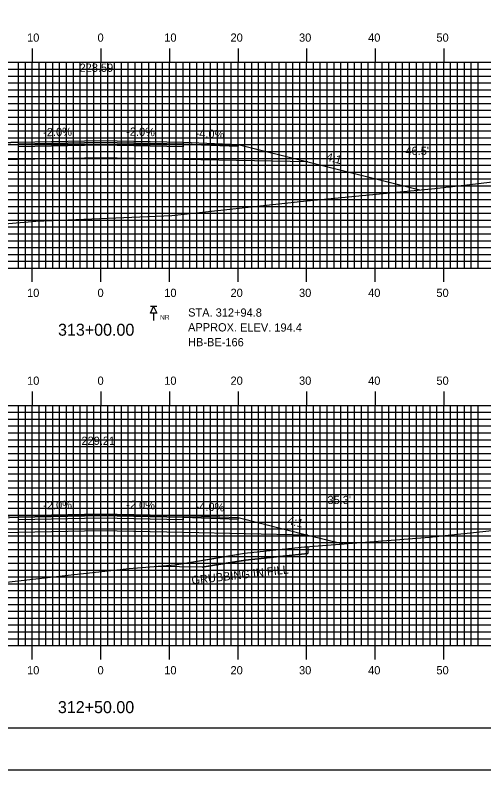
# Model space of a CAD drawing. Extents: x 1818850 to 1819194, y 442591 to 442811.
# Drawn here: x 1819003.7 to 1819072, y 442590.5 to 442700.5 of the extents above; entities that cross this region are included whole.
import ezdxf

# ---------------------------------------------------------------- set-up
doc = ezdxf.new("R2010")
doc.units = 0
for name, color, linetype in [('ANNOTATION', 7, 'Continuous'), ('BORDER', 7, 'Continuous'), ('BORING - NO REFUSAL', 7, 'Continuous'), ('D_Roadway_Centerline', 7, 'Continuous'), ('D_Roadway_Centerline_Text', 7, 'Continuous'), ('D_Roadway_Edge_Shoulder', 7, 'Continuous'), ('D_Roadway_Edge_TW', 7, 'Continuous'), ('D_Roadway_Pavement', 7, 'Continuous'), ('D_Roadway_SlopeLines', 7, 'Continuous'), ('D_Roadway_SubGrade', 7, 'Continuous'), ('D_Text_Standard', 7, 'Continuous'), ('GRUBBING IN FILL', 7, 'Continuous'), ('H_V ANNOTATION', 7, 'Continuous'), ('MAJOR', 7, 'Continuous'), ('MINOR', 7, 'Continuous'), ('PLOT BOUNDARY', 7, 'Continuous'), ('S_Roadway_Centerline', 7, 'Continuous')]:
    doc.layers.add(name, color=color, linetype=linetype)

msp = doc.modelspace()

# ---------------------------------------------------------------- linework, layer by layer
at = {"layer": 'BORDER'}
msp.add_lwpolyline([(1818866.55, 442596.67), (1819186.55, 442596.67), (1819186.55, 442806.67), (1818866.55, 442806.67)], close=True, dxfattribs=at)
at = {"layer": 'BORING - NO REFUSAL'}
for p, q in [((1819024.33, 442658.07), (1819023.37, 442658.07)), ((1819023.85, 442657.11), (1819023.85, 442656.05))]:
    msp.add_line(p, q, dxfattribs=at)
msp.add_lwpolyline([(1819023.85, 442658.07), (1819024.33, 442657.11), (1819023.37, 442657.11)], close=True, dxfattribs=at)
at = {"layer": 'D_Roadway_Centerline'}
for points in [[(1818957.09, 442669.67), (1818984.15, 442678.69), (1818985.98, 442679.15), (1818996.15, 442681.69), (1819004.15, 442682.01), (1819016.15, 442682.25), (1819028.15, 442682.01), (1819036.15, 442681.69), (1819046.33, 442679.15), (1819062.68, 442675.06)], [(1818954.03, 442614.28), (1818984.15, 442624.32), (1818985.98, 442624.77), (1818996.15, 442627.32), (1819004.15, 442627.64), (1819016.15, 442627.88), (1819028.15, 442627.64), (1819036.15, 442627.32), (1819046.33, 442624.77), (1819051.46, 442623.49)]]:
    msp.add_lwpolyline(points, dxfattribs=at)
at = {"layer": 'D_Roadway_Edge_Shoulder'}
for points in [[(1819004.15, 442682.01), (1818996.15, 442681.69), (1818996.15, 442681.44), (1819004.15, 442681.76)], [(1819028.15, 442682.01), (1819036.15, 442681.69), (1819036.15, 442681.44), (1819028.15, 442681.76)], [(1819004.15, 442627.64), (1818996.15, 442627.32), (1818996.15, 442627.07), (1819004.15, 442627.39)], [(1819028.15, 442627.64), (1819036.15, 442627.32), (1819036.15, 442627.07), (1819028.15, 442627.39)]]:
    msp.add_lwpolyline(points, close=True, dxfattribs=at)
at = {"layer": 'D_Roadway_Edge_TW'}
for points in [[(1819004.15, 442681.76), (1819004.15, 442682.01), (1819016.15, 442682.25), (1819028.15, 442682.01), (1819028.15, 442681.76), (1819016.15, 442682)], [(1819004.15, 442627.39), (1819004.15, 442627.64), (1819016.15, 442627.88), (1819028.15, 442627.64), (1819028.15, 442627.39), (1819016.15, 442627.63)]]:
    msp.add_lwpolyline(points, close=True, dxfattribs=at)
at = {"layer": 'D_Roadway_Pavement'}
for points in [[(1819004.15, 442681.34), (1819004.15, 442681.76), (1819016.15, 442682), (1819028.15, 442681.76), (1819028.15, 442681.34), (1819016.15, 442681.58)], [(1819004.15, 442626.97), (1819004.15, 442627.39), (1819016.15, 442627.63), (1819028.15, 442627.39), (1819028.15, 442626.97), (1819016.15, 442627.21)]]:
    msp.add_lwpolyline(points, close=True, dxfattribs=at)
at = {"layer": 'D_Roadway_SlopeLines'}
for points in [[(1819036.15, 442681.69), (1819046.33, 442679.15), (1819062.68, 442675.06)], [(1819036.15, 442627.32), (1819046.33, 442624.77), (1819051.46, 442623.49)]]:
    msp.add_lwpolyline(points, dxfattribs=at)
at = {"layer": 'D_Roadway_SubGrade'}
for points in [[(1819004.15, 442679.51), (1818985.98, 442679.15), (1818996.15, 442681.69), (1818996.15, 442681.44), (1819004.15, 442681.76), (1819016.15, 442682), (1819028.15, 442681.76), (1819036.15, 442681.44), (1819036.15, 442681.69), (1819046.33, 442679.15), (1819028.15, 442679.51), (1819016.15, 442679.75)], [(1819004.15, 442625.14), (1818985.98, 442624.77), (1818996.15, 442627.32), (1818996.15, 442627.07), (1819004.15, 442627.39), (1819016.15, 442627.63), (1819028.15, 442627.39), (1819036.15, 442627.07), (1819036.15, 442627.32), (1819046.33, 442624.77), (1819028.15, 442625.14), (1819016.15, 442625.38)]]:
    msp.add_lwpolyline(points, close=True, dxfattribs=at)
at = {"layer": 'GRUBBING IN FILL'}
msp.add_line((1819046.33, 442623.09), (1819046.33, 442622.08), dxfattribs=at)
msp.add_line((1819046.33, 442623.09), (1819046.33, 442622.08), dxfattribs=at)
msp.add_lwpolyline([(1819046.33, 442623.09), (1819046.33, 442622.08), (1819041.33, 442621.57), (1819037.22, 442621.13), (1819034.08, 442620.61), (1819030.94, 442620.08), (1819024.31, 442620.21), (1819026.94, 442620.43), (1819032.02, 442621.27), (1819037.09, 442622.12), (1819041.21, 442622.56), (1819045.34, 442623.01)], close=True, dxfattribs=at)
msp.add_lwpolyline([(1819046.33, 442623.09), (1819046.33, 442622.08), (1819041.33, 442621.57), (1819037.22, 442621.13), (1819034.08, 442620.61), (1819030.94, 442620.08), (1819024.31, 442620.21), (1819026.94, 442620.43), (1819032.02, 442621.27), (1819037.09, 442622.12), (1819041.21, 442622.56), (1819045.34, 442623.01)], close=True, dxfattribs=at)
msp.add_lwpolyline([(1819030.94, 442620.08), (1819037.22, 442621.13), (1819045.43, 442622.01), (1819046.33, 442622.08)], dxfattribs=at)
msp.add_lwpolyline([(1819030.94, 442620.08), (1819037.22, 442621.13), (1819045.43, 442622.01), (1819046.33, 442622.08)], dxfattribs=at)
at = {"layer": 'MAJOR'}
for p, q in [((1819006.15, 442695.67), (1819006.15, 442693.67)), ((1819016.15, 442695.67), (1819016.15, 442693.67)), ((1819026.15, 442695.67), (1819026.15, 442693.67)), ((1819036.15, 442695.67), (1819036.15, 442693.67)), ((1819046.15, 442695.67), (1819046.15, 442693.67)), ((1819056.15, 442695.67), (1819056.15, 442693.67)), ((1819066.15, 442695.67), (1819066.15, 442693.67)), ((1818876.15, 442693.67), (1819156.15, 442693.67)), ((1818876.15, 442693.67), (1819156.15, 442693.67)), ((1819006.15, 442663.67), (1819006.15, 442693.67)), ((1819016.15, 442663.67), (1819016.15, 442693.67)), ((1819026.15, 442663.67), (1819026.15, 442693.67)), ((1819036.15, 442663.67), (1819036.15, 442693.67)), ((1819046.15, 442663.67), (1819046.15, 442693.67)), ((1819056.15, 442663.67), (1819056.15, 442693.67)), ((1819066.15, 442663.67), (1819066.15, 442693.67)), ((1818876.15, 442688.67), (1819156.15, 442688.67)), ((1818876.15, 442683.67), (1819156.15, 442683.67)), ((1818876.15, 442678.67), (1819156.15, 442678.67)), ((1818876.15, 442673.67), (1819156.15, 442673.67)), ((1818876.15, 442668.67), (1819156.15, 442668.67)), ((1818876.15, 442663.67), (1819156.15, 442663.67)), ((1818876.15, 442663.67), (1819156.15, 442663.67)), ((1819006.15, 442661.66), (1819006.15, 442663.67)), ((1819016.15, 442661.66), (1819016.15, 442663.67)), ((1819026.15, 442661.66), (1819026.15, 442663.67)), ((1819036.15, 442661.66), (1819036.15, 442663.67)), ((1819046.15, 442661.66), (1819046.15, 442663.67)), ((1819056.15, 442661.66), (1819056.15, 442663.67)), ((1819066.15, 442661.66), (1819066.15, 442663.67)), ((1819006.15, 442645.67), (1819006.15, 442643.67)), ((1819016.15, 442645.67), (1819016.15, 442643.67)), ((1819026.15, 442645.67), (1819026.15, 442643.67)), ((1819036.15, 442645.67), (1819036.15, 442643.67)), ((1819046.15, 442645.67), (1819046.15, 442643.67)), ((1819056.15, 442645.67), (1819056.15, 442643.67)), ((1819066.15, 442645.67), (1819066.15, 442643.67)), ((1818876.15, 442643.67), (1819156.15, 442643.67)), ((1818876.15, 442643.67), (1819156.15, 442643.67)), ((1819006.15, 442608.67), (1819006.15, 442643.67)), ((1819016.15, 442608.67), (1819016.15, 442643.67)), ((1819026.15, 442608.67), (1819026.15, 442643.67)), ((1819036.15, 442608.67), (1819036.15, 442643.67)), ((1819046.15, 442608.67), (1819046.15, 442643.67)), ((1819056.15, 442608.67), (1819056.15, 442643.67)), ((1819066.15, 442608.67), (1819066.15, 442643.67)), ((1818876.15, 442638.67), (1819156.15, 442638.67)), ((1818876.15, 442633.67), (1819156.15, 442633.67)), ((1818876.15, 442628.67), (1819156.15, 442628.67)), ((1818876.15, 442623.67), (1819156.15, 442623.67)), ((1818876.15, 442618.67), (1819156.15, 442618.67)), ((1818876.15, 442613.67), (1819156.15, 442613.67)), ((1818876.15, 442608.67), (1819156.15, 442608.67)), ((1818876.15, 442608.67), (1819156.15, 442608.67)), ((1819006.15, 442606.66), (1819006.15, 442608.67)), ((1819016.15, 442606.66), (1819016.15, 442608.67)), ((1819026.15, 442606.66), (1819026.15, 442608.67)), ((1819036.15, 442606.66), (1819036.15, 442608.67)), ((1819046.15, 442606.66), (1819046.15, 442608.67)), ((1819056.15, 442606.66), (1819056.15, 442608.67)), ((1819066.15, 442606.66), (1819066.15, 442608.67))]:
    msp.add_line(p, q, dxfattribs=at)
at = {"layer": 'MINOR'}
for p, q in [((1819004.15, 442663.67), (1819004.15, 442693.67)), ((1819005.15, 442663.67), (1819005.15, 442693.67)), ((1819007.15, 442663.67), (1819007.15, 442693.67)), ((1819008.15, 442663.67), (1819008.15, 442693.67)), ((1819009.15, 442663.67), (1819009.15, 442693.67)), ((1819010.15, 442663.67), (1819010.15, 442693.67)), ((1819011.15, 442663.67), (1819011.15, 442693.67)), ((1819012.15, 442663.67), (1819012.15, 442693.67)), ((1819013.15, 442663.67), (1819013.15, 442693.67)), ((1819014.15, 442663.67), (1819014.15, 442693.67)), ((1819015.15, 442663.67), (1819015.15, 442693.67)), ((1819017.15, 442663.67), (1819017.15, 442693.67)), ((1819018.15, 442663.67), (1819018.15, 442693.67)), ((1819019.15, 442663.67), (1819019.15, 442693.67)), ((1819020.15, 442663.67), (1819020.15, 442693.67)), ((1819021.15, 442663.67), (1819021.15, 442693.67)), ((1819022.15, 442663.67), (1819022.15, 442693.67)), ((1819023.15, 442663.67), (1819023.15, 442693.67)), ((1819024.15, 442663.67), (1819024.15, 442693.67)), ((1819025.15, 442663.67), (1819025.15, 442693.67)), ((1819027.15, 442663.67), (1819027.15, 442693.67)), ((1819028.15, 442663.67), (1819028.15, 442693.67)), ((1819029.15, 442663.67), (1819029.15, 442693.67)), ((1819030.15, 442663.67), (1819030.15, 442693.67)), ((1819031.15, 442663.67), (1819031.15, 442693.67)), ((1819032.15, 442663.67), (1819032.15, 442693.67)), ((1819033.15, 442663.67), (1819033.15, 442693.67)), ((1819034.15, 442663.67), (1819034.15, 442693.67)), ((1819035.15, 442663.67), (1819035.15, 442693.67)), ((1819037.15, 442663.67), (1819037.15, 442693.67)), ((1819038.15, 442663.67), (1819038.15, 442693.67)), ((1819039.15, 442663.67), (1819039.15, 442693.67)), ((1819040.15, 442663.67), (1819040.15, 442693.67)), ((1819041.15, 442663.67), (1819041.15, 442693.67)), ((1819042.15, 442663.67), (1819042.15, 442693.67)), ((1819043.15, 442663.67), (1819043.15, 442693.67)), ((1819044.15, 442663.67), (1819044.15, 442693.67)), ((1819045.15, 442663.67), (1819045.15, 442693.67)), ((1819047.15, 442663.67), (1819047.15, 442693.67)), ((1819048.15, 442663.67), (1819048.15, 442693.67)), ((1819049.15, 442663.67), (1819049.15, 442693.67)), ((1819050.15, 442663.67), (1819050.15, 442693.67)), ((1819051.15, 442663.67), (1819051.15, 442693.67)), ((1819052.15, 442663.67), (1819052.15, 442693.67)), ((1819053.15, 442663.67), (1819053.15, 442693.67)), ((1819054.15, 442663.67), (1819054.15, 442693.67)), ((1819055.15, 442663.67), (1819055.15, 442693.67)), ((1819057.15, 442663.67), (1819057.15, 442693.67)), ((1819058.15, 442663.67), (1819058.15, 442693.67)), ((1819059.15, 442663.67), (1819059.15, 442693.67)), ((1819060.15, 442663.67), (1819060.15, 442693.67)), ((1819061.15, 442663.67), (1819061.15, 442693.67)), ((1819062.15, 442663.67), (1819062.15, 442693.67)), ((1819063.15, 442663.67), (1819063.15, 442693.67)), ((1819064.15, 442663.67), (1819064.15, 442693.67)), ((1819065.15, 442663.67), (1819065.15, 442693.67)), ((1819067.15, 442663.67), (1819067.15, 442693.67)), ((1819068.15, 442663.67), (1819068.15, 442693.67)), ((1819069.15, 442663.67), (1819069.15, 442693.67)), ((1819070.15, 442663.67), (1819070.15, 442693.67)), ((1819071.15, 442663.67), (1819071.15, 442693.67)), ((1818876.15, 442692.67), (1819156.15, 442692.67)), ((1818876.15, 442691.67), (1819156.15, 442691.67)), ((1818876.15, 442690.67), (1819156.15, 442690.67)), ((1818876.15, 442689.67), (1819156.15, 442689.67)), ((1818876.15, 442687.67), (1819156.15, 442687.67)), ((1818876.15, 442686.67), (1819156.15, 442686.67)), ((1818876.15, 442685.67), (1819156.15, 442685.67)), ((1818876.15, 442684.67), (1819156.15, 442684.67)), ((1818876.15, 442682.67), (1819156.15, 442682.67)), ((1818876.15, 442681.67), (1819156.15, 442681.67)), ((1818876.15, 442680.67), (1819156.15, 442680.67)), ((1818876.15, 442679.67), (1819156.15, 442679.67)), ((1818876.15, 442677.67), (1819156.15, 442677.67)), ((1818876.15, 442676.67), (1819156.15, 442676.67)), ((1818876.15, 442675.67), (1819156.15, 442675.67)), ((1818876.15, 442674.67), (1819156.15, 442674.67)), ((1818876.15, 442672.67), (1819156.15, 442672.67)), ((1818876.15, 442671.67), (1819156.15, 442671.67)), ((1818876.15, 442670.67), (1819156.15, 442670.67)), ((1818876.15, 442669.67), (1819156.15, 442669.67)), ((1818876.15, 442667.67), (1819156.15, 442667.67)), ((1818876.15, 442666.67), (1819156.15, 442666.67)), ((1818876.15, 442665.67), (1819156.15, 442665.67)), ((1818876.15, 442664.67), (1819156.15, 442664.67)), ((1819004.15, 442608.67), (1819004.15, 442643.67)), ((1819005.15, 442608.67), (1819005.15, 442643.67)), ((1819007.15, 442608.67), (1819007.15, 442643.67)), ((1819008.15, 442608.67), (1819008.15, 442643.67)), ((1819009.15, 442608.67), (1819009.15, 442643.67)), ((1819010.15, 442608.67), (1819010.15, 442643.67)), ((1819011.15, 442608.67), (1819011.15, 442643.67)), ((1819012.15, 442608.67), (1819012.15, 442643.67)), ((1819013.15, 442608.67), (1819013.15, 442643.67)), ((1819014.15, 442608.67), (1819014.15, 442643.67)), ((1819015.15, 442608.67), (1819015.15, 442643.67)), ((1819017.15, 442608.67), (1819017.15, 442643.67)), ((1819018.15, 442608.67), (1819018.15, 442643.67)), ((1819019.15, 442608.67), (1819019.15, 442643.67)), ((1819020.15, 442608.67), (1819020.15, 442643.67)), ((1819021.15, 442608.67), (1819021.15, 442643.67)), ((1819022.15, 442608.67), (1819022.15, 442643.67)), ((1819023.15, 442608.67), (1819023.15, 442643.67)), ((1819024.15, 442608.67), (1819024.15, 442643.67)), ((1819025.15, 442608.67), (1819025.15, 442643.67)), ((1819027.15, 442608.67), (1819027.15, 442643.67)), ((1819028.15, 442608.67), (1819028.15, 442643.67)), ((1819029.15, 442608.67), (1819029.15, 442643.67)), ((1819030.15, 442608.67), (1819030.15, 442643.67)), ((1819031.15, 442608.67), (1819031.15, 442643.67)), ((1819032.15, 442608.67), (1819032.15, 442643.67)), ((1819033.15, 442608.67), (1819033.15, 442643.67)), ((1819034.15, 442608.67), (1819034.15, 442643.67)), ((1819035.15, 442608.67), (1819035.15, 442643.67)), ((1819037.15, 442608.67), (1819037.15, 442643.67)), ((1819038.15, 442608.67), (1819038.15, 442643.67)), ((1819039.15, 442608.67), (1819039.15, 442643.67)), ((1819040.15, 442608.67), (1819040.15, 442643.67)), ((1819041.15, 442608.67), (1819041.15, 442643.67)), ((1819042.15, 442608.67), (1819042.15, 442643.67)), ((1819043.15, 442608.67), (1819043.15, 442643.67)), ((1819044.15, 442608.67), (1819044.15, 442643.67)), ((1819045.15, 442608.67), (1819045.15, 442643.67)), ((1819047.15, 442608.67), (1819047.15, 442643.67)), ((1819048.15, 442608.67), (1819048.15, 442643.67)), ((1819049.15, 442608.67), (1819049.15, 442643.67)), ((1819050.15, 442608.67), (1819050.15, 442643.67)), ((1819051.15, 442608.67), (1819051.15, 442643.67)), ((1819052.15, 442608.67), (1819052.15, 442643.67)), ((1819053.15, 442608.67), (1819053.15, 442643.67)), ((1819054.15, 442608.67), (1819054.15, 442643.67)), ((1819055.15, 442608.67), (1819055.15, 442643.67)), ((1819057.15, 442608.67), (1819057.15, 442643.67)), ((1819058.15, 442608.67), (1819058.15, 442643.67)), ((1819059.15, 442608.67), (1819059.15, 442643.67)), ((1819060.15, 442608.67), (1819060.15, 442643.67)), ((1819061.15, 442608.67), (1819061.15, 442643.67)), ((1819062.15, 442608.67), (1819062.15, 442643.67)), ((1819063.15, 442608.67), (1819063.15, 442643.67)), ((1819064.15, 442608.67), (1819064.15, 442643.67)), ((1819065.15, 442608.67), (1819065.15, 442643.67)), ((1819067.15, 442608.67), (1819067.15, 442643.67)), ((1819068.15, 442608.67), (1819068.15, 442643.67)), ((1819069.15, 442608.67), (1819069.15, 442643.67)), ((1819070.15, 442608.67), (1819070.15, 442643.67)), ((1819071.15, 442608.67), (1819071.15, 442643.67)), ((1818876.15, 442642.67), (1819156.15, 442642.67)), ((1818876.15, 442641.67), (1819156.15, 442641.67)), ((1818876.15, 442640.67), (1819156.15, 442640.67)), ((1818876.15, 442639.67), (1819156.15, 442639.67)), ((1818876.15, 442637.67), (1819156.15, 442637.67)), ((1818876.15, 442636.67), (1819156.15, 442636.67)), ((1818876.15, 442635.67), (1819156.15, 442635.67)), ((1818876.15, 442634.67), (1819156.15, 442634.67)), ((1818876.15, 442632.67), (1819156.15, 442632.67)), ((1818876.15, 442631.67), (1819156.15, 442631.67)), ((1818876.15, 442630.67), (1819156.15, 442630.67)), ((1818876.15, 442629.67), (1819156.15, 442629.67)), ((1818876.15, 442627.67), (1819156.15, 442627.67)), ((1818876.15, 442626.67), (1819156.15, 442626.67)), ((1818876.15, 442625.67), (1819156.15, 442625.67)), ((1818876.15, 442624.67), (1819156.15, 442624.67)), ((1818876.15, 442622.67), (1819156.15, 442622.67)), ((1818876.15, 442621.67), (1819156.15, 442621.67)), ((1818876.15, 442620.67), (1819156.15, 442620.67)), ((1818876.15, 442619.67), (1819156.15, 442619.67)), ((1818876.15, 442617.67), (1819156.15, 442617.67)), ((1818876.15, 442616.67), (1819156.15, 442616.67)), ((1818876.15, 442615.67), (1819156.15, 442615.67)), ((1818876.15, 442614.67), (1819156.15, 442614.67)), ((1818876.15, 442612.67), (1819156.15, 442612.67)), ((1818876.15, 442611.67), (1819156.15, 442611.67)), ((1818876.15, 442610.67), (1819156.15, 442610.67)), ((1818876.15, 442609.67), (1819156.15, 442609.67))]:
    msp.add_line(p, q, dxfattribs=at)
at = {"layer": 'PLOT BOUNDARY'}
msp.add_lwpolyline([(1818850.36, 442590.55), (1819190.36, 442590.55), (1819190.36, 442810.55), (1818850.36, 442810.55)], close=True, dxfattribs=at)
at = {"layer": 'S_Roadway_Centerline'}
for points in [[(1818876.15, 442670.16), (1818879.81, 442670.23), (1818880.03, 442670.23), (1818909.11, 442670.03), (1818914.93, 442670.06), (1818918.93, 442670.01), (1818929.9, 442669.84), (1818932.68, 442669.8), (1818943.95, 442669.74), (1818957.52, 442669.67), (1818963.63, 442669.73), (1818972.89, 442669.72), (1818980.88, 442669.33), (1818987.41, 442669.1), (1818998.09, 442669.77), (1819006.66, 442670.52), (1819026.49, 442671.35), (1819039.87, 442672.8), (1819045.19, 442673.38), (1819064.86, 442675.27), (1819066.46, 442675.46), (1819066.98, 442675.51), (1819070.78, 442675.98), (1819083.88, 442677.52)], [(1818945.66, 442614.26), (1818966.04, 442614.3), (1818977.23, 442615.31), (1818984.64, 442616.22), (1818994.21, 442617.1), (1818997.18, 442617.31), (1819010.97, 442618.9), (1819020.28, 442619.88), (1819026.94, 442620.43), (1819037.09, 442622.12), (1819045.34, 442623.01), (1819058.49, 442624.04), (1819064.07, 442624.48), (1819079.13, 442626.05)]]:
    msp.add_lwpolyline(points, dxfattribs=at)

# ---------------------------------------------------------------- texts
at = {"layer": 'ANNOTATION'}
for s, rotation, p in [('-2.0%', 1.1458, (1819007.76, 442682.88)), ('-2.0%', 358.8542, (1819019.84, 442682.98)), ('-4.0%', 357.7094, (1819029.94, 442682.74)), ('4:1', 345.9638, (1819048.92, 442679.36)), ('-2.0%', 1.1458, (1819007.76, 442628.51)), ('-2.0%', 358.8542, (1819019.84, 442628.6)), ('-4.0%', 357.7094, (1819029.94, 442628.37)), ('4:1', 345.9638, (1819043.31, 442626.39))]:
    msp.add_text(s, height=1.2, rotation=rotation, dxfattribs=at).set_placement(p)
at = {"layer": 'BORING - NO REFUSAL'}
for s, p in [('STA. 312+94.8', (1819028.88, 442656.62)), ('APPROX. ELEV. 194.4', (1819028.87, 442654.46)), ('HB-BE-166', (1819028.87, 442652.3))]:
    msp.add_text(s, height=1.2, rotation=359.8142, dxfattribs=at).set_placement(p)
msp.add_text('NR', height=0.7, dxfattribs=at).set_placement((1819024.78, 442656.15))
at = {"layer": 'D_Roadway_Centerline'}
for s, p in [('C', (1819016.15, 442682.25)), ('L', (1819016.15, 442682.24)), ('C', (1819016.15, 442627.88)), ('L', (1819016.15, 442627.87))]:
    msp.add_text(s, height=0.0146, dxfattribs=at).set_placement(p)
at = {"layer": 'D_Roadway_Centerline_Text'}
for s, p in [('228.59', (1819013.05, 442692.28)), ('229.21', (1819013.33, 442637.91))]:
    msp.add_text(s, height=1.2, dxfattribs=at).set_placement(p)
at = {"layer": 'D_Text_Standard'}
for s, p in [("46.5'", (1819060.56, 442680.16)), ("35.3'", (1819049.2, 442629.29))]:
    msp.add_text(s, height=1.2, dxfattribs=at).set_placement(p)
at = {"layer": 'GRUBBING IN FILL'}
msp.add_text('GRUBBING IN FILL', height=1.2, rotation=6.4693, dxfattribs=at).set_placement((1819029.44, 442617.58))
at = {"layer": 'H_V ANNOTATION'}
for s, height, p in [('10', 1.2, (1819005.4, 442696.67)), ('0', 1.2, (1819015.67, 442696.67)), ('10', 1.2, (1819025.4, 442696.67)), ('20', 1.2, (1819035.06, 442696.67)), ('30', 1.2, (1819045.05, 442696.67)), ('40', 1.2, (1819055.12, 442696.67)), ('50', 1.2, (1819065.08, 442696.67)), ('10', 1.2, (1819005.4, 442659.47)), ('0', 1.2, (1819015.67, 442659.47)), ('10', 1.2, (1819025.4, 442659.47)), ('20', 1.2, (1819035.06, 442659.47)), ('30', 1.2, (1819045.05, 442659.47)), ('40', 1.2, (1819055.12, 442659.47)), ('50', 1.2, (1819065.08, 442659.47)), ('313+00.00', 1.75, (1819009.91, 442653.82)), ('10', 1.2, (1819005.4, 442646.67)), ('0', 1.2, (1819015.67, 442646.67)), ('10', 1.2, (1819025.4, 442646.67)), ('20', 1.2, (1819035.06, 442646.67)), ('30', 1.2, (1819045.05, 442646.67)), ('40', 1.2, (1819055.12, 442646.67)), ('50', 1.2, (1819065.08, 442646.67)), ('10', 1.2, (1819005.4, 442604.47)), ('0', 1.2, (1819015.67, 442604.47)), ('10', 1.2, (1819025.4, 442604.47)), ('20', 1.2, (1819035.06, 442604.47)), ('30', 1.2, (1819045.05, 442604.47)), ('40', 1.2, (1819055.12, 442604.47)), ('50', 1.2, (1819065.08, 442604.47)), ('312+50.00', 1.75, (1819009.89, 442598.82))]:
    msp.add_text(s, height=height, dxfattribs=at).set_placement(p)

doc.saveas('drawing.dxf')
